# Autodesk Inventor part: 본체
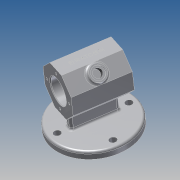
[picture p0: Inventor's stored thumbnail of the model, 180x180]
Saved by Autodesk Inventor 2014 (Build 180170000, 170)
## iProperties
Created: 2021-02
Part Number: 본체
Material: 알루미늄 6061
Document SubType Name: Modeling
Designer: kb542-22
Density: 2.71 g/cm^3
Appearance: 알루미늄 - 평지
Mass: 558.374 g
Surface Area: 514.422 cm^2
Volume: 206.042 cm^3
Author: kb542-22
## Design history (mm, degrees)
sketch "스케치1" dims "d9" = 58
  geometry: L1 (29, -12.012)-(12.012, -29); L2 (12.012, -29)-(-12.012, -29); L3 (-12.012, -29)-(-29, -12.012); L4 (-29, -12.012)-(-29, 12.012); L5 (-29, 12.012)-(-12.012, 29); L6 (-12.012, 29)-(12.012, 29); L7 (12.012, 29)-(29, 12.012); L8 (29, 12.012)-(29, -12.012); 4 further points
  constraints: 16 end point, 2 vertical alignment, 1 coincident, 1 horizontal alignment, 1 midpoint, 1 vertical, 20 other
extrude "돌출1" new body sketch "스케치1" stored distance "d10" = 70; taper "d11" = 0 deg
sketch "스케치2"
  geometry: L1 (12.012, 35)-(12.012, -35) reference; L2 (-12.012, 35)-(12.012, 35) reference; L3 (-12.012, 35)-(-12.012, -35) reference; L4 (12.012, -35)-(-12.012, -35) reference; L5 (0, 35)-(0, -35); L6 (0, 35)-(16, 35); L7 (16, 35)-(16, 23.3); L8 (15.7, 23)-(14, 23); L9 (14, 23)-(14, 20); L10 (14, 20)-(22, 20); L11 (22, 20)-(22, -20); L12 (22, -20)-(14, -20); L13 (14, -20)-(14, -23); L14 (14, -23)-(15.7, -23); L15 (16, -23.3)-(16, -35); L16 (16, -35)-(0, -35); A1 r 0.3 centre (15.7, 23.3) between (15.7, 23) and (16, 23.3); A2 r 0.3 centre (15.7, -23.3) between (16, -23.3) and (15.7, -23); 2 further points
  constraints: 24 end point, 6 perpendicular, 4 parallel, 4 point on circle, 4 tangent, 3 point on line, 2 centre point, 2 midpoint, 1 collinear, 1 equal radius
  dimensions: "d12" = 12 distance from line of point (16, 23) L6; "d13" = 12 distance between parallel lines of L16 L14; "d14" = 28 diameter of L9 L5; "d15" = 44 diameter of L11 L5; "d16" = 32 diameter of L7 L5; "d17" = 28 diameter of L13 L5; "d18" = 32 diameter of L15 L5; "d19" = 40 distance between parallel lines of L12 L10; "d20" = 3 distance between parallel lines of L10 L8 (derived); "d21" = 0.3 radius of A1
revolve "회전1" sketch "스케치2" stored, may be unused: angle "d22" = 90 deg
sketch "스케치3" dims "d23" = 46
  geometry: C1 r 16 at (0, 0) reference; 2 further points
  constraints: 2 vertical alignment, 1 coincident, 2 other
hole "구멍1" sketch "스케치3" at (0, 23) diameter "d24" = 3.242; stored, may be unused: countersink angle "d28" = 90 deg, drill point angle "d30" = 118 deg; dims "d25" = 8, "d26" = 4, "d27" = 2, "d29" = 10
sketch "스케치4"
  geometry: L1 (0, 0)-(0, 44.719); L2 (0, 0)-(24.042, 24.042); L3 (12.012, 29)-(29, 12.012) reference; C1 r 16 at (0, 0) reference; 1 further point
  constraints: 4 end point, 1 vertical
  dimensions: "d34" = 45 deg angle of L2 L1; "d35" = 5 distance from line of L3 L2.end
node "작업 평면1"
sketch "스케치5"
  geometry: C1 r 10 at (0, 0); 1 further point
  constraints: 1 centre point, 1 coincident
  dimensions: "d36" = 20 diameter of C1
extrude "돌출2" join sketch "스케치5" stored distance "d37" = 70; taper "d38" = 0 deg
node "작업 평면2"
sketch "스케치6"
  geometry: L1 (-29, 35)-(-29, -35) reference; L2 (29, 35)-(29, -35) reference; L3 (12.012, -35)-(-12.012, -35) reference; L4 (-12.012, 35)-(12.012, 35) reference; C1 r 52 at (0, 0); C2 r 4.5 at (-41, 0); C3 r 4.5 at (0, 41); C4 r 4.5 at (0, -41); C5 r 4.5 at (41, 0); A1 r 41 centre (0, 0) between (-41, 0) and (0, 41); 1 further point
  constraints: 6 centre point, 4 point on circle, 3 equal radius, 2 coincident, 2 horizontal alignment, 2 vertical alignment
  dimensions: "d40" = 104 diameter of C1; "d41" = 82 diameter of A1; "d42" = 9 diameter of C4
extrude "돌출3" join sketch "스케치6" distance "d43" = 10; taper "d44" = 0 deg
sketch "스케치7"
  geometry: L1 (28, -5)-(-28, -5); L2 (-28, -5)-(-28, 5); L3 (-28, 5)-(28, 5); L4 (28, 5)-(28, -5); L5 (-35, 12.012)-(35, 12.012) reference; L6 (-35, -12.012)-(-35, 12.012) reference; L7 (35, -12.012)-(-35, -12.012) reference; L8 (35, 12.012)-(35, -12.012) reference; C1 r 52 at (0, 0) reference; 2 further points
  constraints: 8 end point, 2 midpoint, 2 parallel, 1 horizontal, 1 horizontal alignment, 1 perpendicular, 1 vertical alignment
  dimensions: "d45" = 10 distance between parallel lines of L3 L1; "d46" = 56 distance between parallel lines of L4 L2
extrude "돌출4" join sketch "스케치7" stored distance "d47" = 10; taper "d48" = 0 deg
hole "구멍2" diameter "d51" = 10.917; stored, may be unused: countersink angle "d55" = 90 deg, drill point angle "d57" = 0 deg; dims "d49" = 10, "d50" = 10, "d52" = 8, "d53" = 16, "d54" = 2, "d56" = 10
node "작업 평면3"
sketch "스케치8"
  geometry: L1 (70, 0)-(0, 0) reference; L2 (70, 24.024)-(70, 0) reference; L3 (0, -16.988)-(70, -16.988) reference; 2 further points
  constraints: 1 other
  dimensions: "d59" = 35 distance from line of L2 point (35, 12.405); "d60" = 29 distance from line of L3 point (35, 12.012) (derived)
feature "엠보싱1" sketch "스케치8" dims "d9" = 58, "d12" = 12, "d13" = 12, "d14" = 28, "d15" = 44, "d16" = 32, "d17" = 28, "d18" = 32, "d19" = 40, "d20" = 3 (derived), "d21" = 0.3, "d61" = 0.5, "d62" = 0
fillet "모깎기1" dims "d63" = 3
fillet "모깎기2" dims "d64" = 3
chamfer "모따기1" distance "d65" = 1; stored, may be unused: second distance "d66" = 2, angle "d67" = 45 deg
node "솔리드1"
pattern_circular "원형 패턴1" dims angle "d32" = 360 deg
mirror "대칭1"
node "투영된 루프1"
node "투영된 루프2"
other parameters: "d39" = -62, "d58" = 33
